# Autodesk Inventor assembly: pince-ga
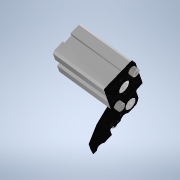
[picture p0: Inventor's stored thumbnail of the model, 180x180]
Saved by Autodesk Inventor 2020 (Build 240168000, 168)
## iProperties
Created: 2023-10
Part Number: pince-ga
Document SubType Name: Assembly
Designer: bruno
Author: bruno
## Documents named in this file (6)
- C:\Users\bruno\Documents\1-Cours-2023-24\Maquettes-Inventor\Pince-robot-Dobot\HS422\pince-ga.iam
- C:\Users\bruno\Documents\1-Cours-2023-24\Maquettes-Inventor\Pince-robot-Dobot\pince-g.ipt
- C:\Users\bruno\Documents\1-Cours-2023-24\Maquettes-Inventor\Pince-robot-Dobot\Douille.ipt
- C:\Users\bruno\Documents\1-Cours-2023-24\Maquettes-Inventor\Pince-robot-Dobot\corps-verin.ipt
- C:\Users\bruno\Documents\Inventor\Content Center Files\R2020\fr-FR\KS B 1003\KS B 1003 - M 4 x 8.ipt
- C:\Users\bruno\Documents\Inventor\Content Center Files\R2020\fr-FR\KS B 1003\KS B 1003 - M 3 x 10.ipt
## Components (6 placed, 5 different names)
1. pince-g:1 — Placage:1, Affleurement:1, Placage:2, Placage:3, Angle:1, Logement:1, Logement:2, Logement:3
2. Douille:1 — Placage:1, Affleurement:1
3. corps-verin:1 — Placage:2, Placage:3, Angle:1
4. KS B 1003 - Métrique M 4 x 8:1 — Logement:1
5. KS B 1003 - Métrique M 4 x 8:2 — Logement:2
6. KS B 1003 - Métrique M 3 x 10:1 — Logement:3
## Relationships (8: Mate 3, Insert 3, Flush 1, Angle 1)
- Placage:1 [Mate]: pince-g:1 ↔ Douille:1
- Affleurement:1 [Flush]: pince-g:1 ↔ Douille:1
- Placage:2 [Mate]: pince-g:1 ↔ corps-verin:1
- Placage:3 [Mate]: pince-g:1 ↔ corps-verin:1
- Angle:1: pince-g:1 ↔ corps-verin:1
- Logement:1 [Insert]: pince-g:1 ↔ KS B 1003 - Métrique M 4 x 8:1
- Logement:2 [Insert]: pince-g:1 ↔ KS B 1003 - Métrique M 4 x 8:2
- Logement:3 [Insert]: pince-g:1 ↔ KS B 1003 - Métrique M 3 x 10:1
